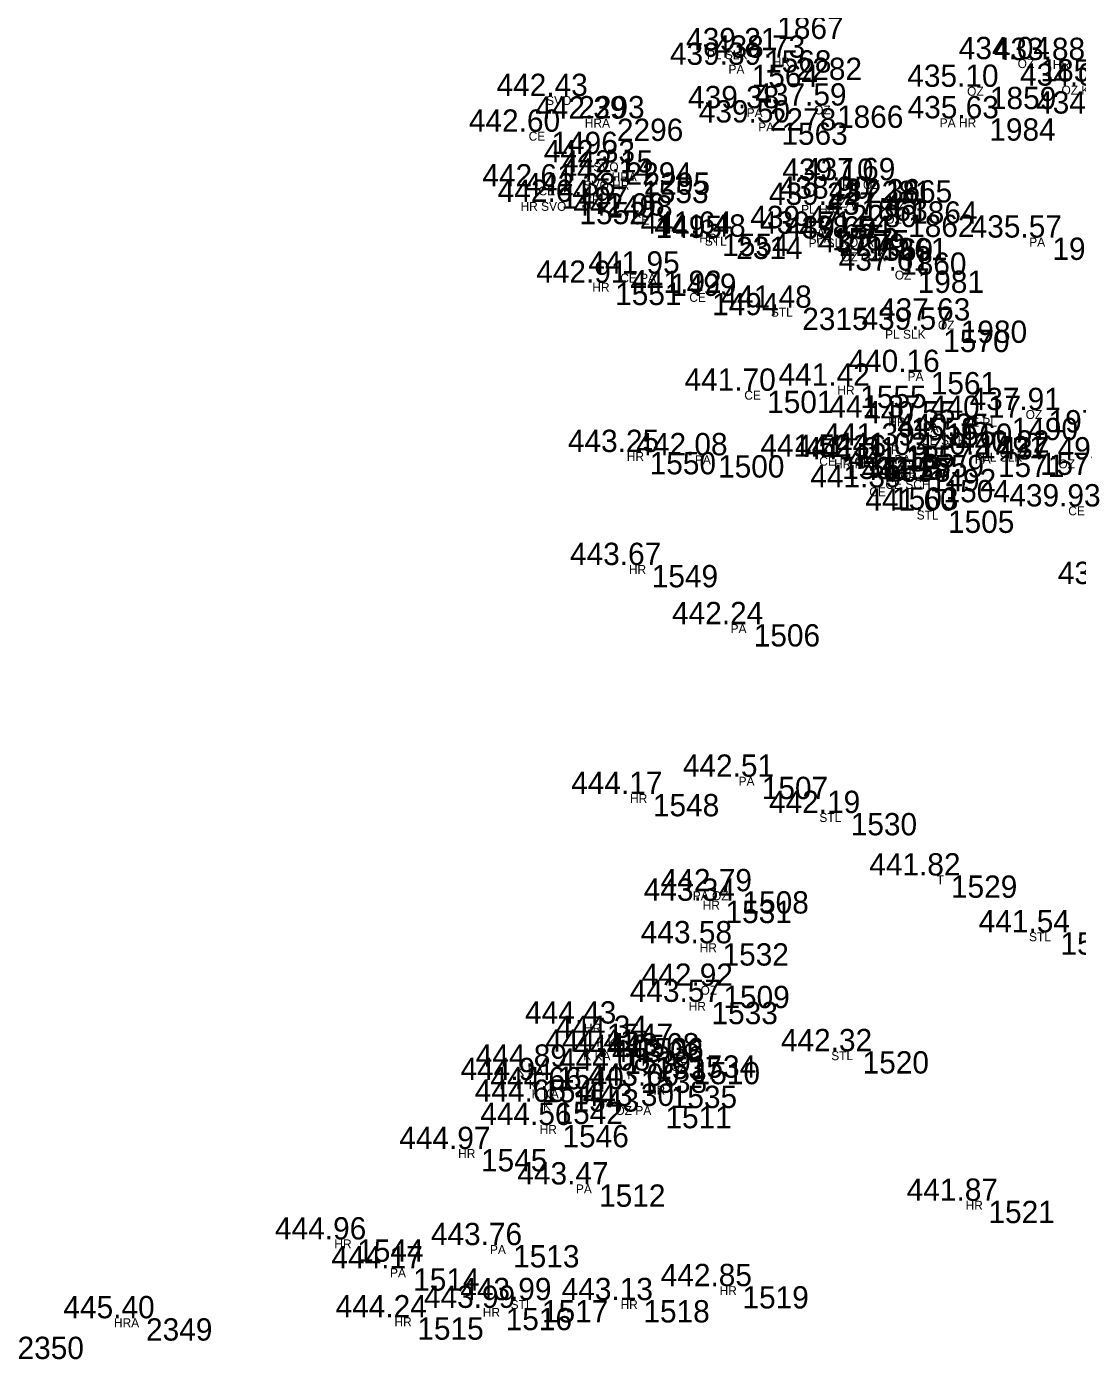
# Model space of a CAD drawing. Extents: x -639390 to -639075, y -1138747 to -1138358.
# Drawn here: x -639325.37 to -639290.05, y -1138561.86 to -1138517.05 of the extents above; entities that cross this region are included whole.
import ezdxf

# ---------------------------------------------------------------- set-up
doc = ezdxf.new("R2010")
doc.units = 0
for name, color, linetype in [('Vrstva 11', 7, 'Continuous'), ('Vrstva 12', 7, 'Continuous'), ('Vrstva 13', 7, 'Continuous'), ('Vrstva 57', 7, 'Continuous')]:
    doc.layers.add(name, color=color, linetype=linetype)

msp = doc.modelspace()

# ---------------------------------------------------------------- linework, layer by layer
at = {"layer": 'Vrstva 11'}
for p, q in [((-639300.83, -1138517.84), (-639300.83, -1138517.84)), ((-639301.28, -1138518.33), (-639301.28, -1138518.33)), ((-639299.8, -1138518.09), (-639299.8, -1138518.09)), ((-639291.57, -1138518.14), (-639291.57, -1138518.14)), ((-639290.39, -1138518.17), (-639290.39, -1138518.17)), ((-639307.11, -1138519.38), (-639307.11, -1138519.38)), ((-639293.27, -1138519.07), (-639293.27, -1138519.07)), ((-639300.67, -1138519.79), (-639300.67, -1138519.79)), ((-639298.41, -1138519.7), (-639298.41, -1138519.7)), ((-639305.81, -1138520.14), (-639305.81, -1138520.14)), ((-639300.28, -1138520.27), (-639300.28, -1138520.27)), ((-639293.29, -1138520.13), (-639293.29, -1138520.13)), ((-639308.01, -1138520.58), (-639308.01, -1138520.58)), ((-639305.52, -1138521.61), (-639305.52, -1138521.61)), ((-639304.91, -1138521.95), (-639304.91, -1138521.95)), ((-639307.68, -1138522.42), (-639307.68, -1138522.42)), ((-639304.96, -1138522.23), (-639304.96, -1138522.23)), ((-639297.47, -1138522.23), (-639297.47, -1138522.23)), ((-639296.77, -1138522.21), (-639296.77, -1138522.21)), ((-639307.07, -1138522.94), (-639307.07, -1138522.94)), ((-639306.17, -1138522.72), (-639306.17, -1138522.72)), ((-639297.59, -1138522.83), (-639297.59, -1138522.83)), ((-639295.92, -1138522.92), (-639295.92, -1138522.92)), ((-639304.51, -1138523.4), (-639304.51, -1138523.4)), ((-639297.95, -1138523.04), (-639297.95, -1138523.04)), ((-639296.02, -1138523.37), (-639296.02, -1138523.37)), ((-639298.58, -1138523.82), (-639298.58, -1138523.82)), ((-639302.27, -1138524.01), (-639302.27, -1138524.01)), ((-639301.8, -1138524.11), (-639301.8, -1138524.11)), ((-639298.34, -1138524.01), (-639298.34, -1138524.01)), ((-639297.41, -1138524.17), (-639297.41, -1138524.17)), ((-639296.93, -1138524.15), (-639296.93, -1138524.15)), ((-639291.17, -1138524.14), (-639291.17, -1138524.14)), ((-639296.29, -1138524.64), (-639296.29, -1138524.64)), ((-639304.02, -1138525.35), (-639304.02, -1138525.35)), ((-639295.7, -1138525.25), (-639295.7, -1138525.25)), ((-639305.87, -1138525.66), (-639305.87, -1138525.66)), ((-639302.61, -1138526), (-639302.61, -1138526)), ((-639299.58, -1138526.5), (-639299.58, -1138526.5)), ((-639294.25, -1138526.93), (-639294.25, -1138526.93)), ((-639294.84, -1138527.24), (-639294.84, -1138527.24)), ((-639295.26, -1138528.66), (-639295.26, -1138528.66)), ((-639297.63, -1138529.12), (-639297.63, -1138529.12)), ((-639300.76, -1138529.29), (-639300.76, -1138529.29)), ((-639291.3, -1138529.94), (-639291.3, -1138529.94)), ((-639295.92, -1138530.19), (-639295.92, -1138530.19)), ((-639294.75, -1138530.39), (-639294.75, -1138530.39)), ((-639292.54, -1138530.2), (-639292.54, -1138530.2)), ((-639293.63, -1138530.81), (-639293.63, -1138530.81)), ((-639304.71, -1138531.35), (-639304.71, -1138531.35)), ((-639302.41, -1138531.46), (-639302.41, -1138531.46)), ((-639296.12, -1138531.13), (-639296.12, -1138531.13)), ((-639295.7, -1138531.45), (-639295.7, -1138531.45)), ((-639293, -1138531.44), (-639293, -1138531.44)), ((-639291.59, -1138531.37), (-639291.59, -1138531.37)), ((-639298.24, -1138531.51), (-639298.24, -1138531.51)), ((-639297.06, -1138531.52), (-639297.06, -1138531.52)), ((-639296.83, -1138531.6), (-639296.83, -1138531.6)), ((-639295.29, -1138531.92), (-639295.29, -1138531.92)), ((-639290.2, -1138531.6), (-639290.2, -1138531.6)), ((-639294.83, -1138532.29), (-639294.83, -1138532.29)), ((-639296.56, -1138532.54), (-639296.56, -1138532.54)), ((-639294.68, -1138533.32), (-639294.68, -1138533.32)), ((-639304.64, -1138535.15), (-639304.64, -1138535.15)), ((-639301.21, -1138537.14), (-639301.21, -1138537.14)), ((-639300.94, -1138542.27), (-639300.94, -1138542.27)), ((-639304.6, -1138542.85), (-639304.6, -1138542.85)), ((-639297.95, -1138543.49), (-639297.95, -1138543.49)), ((-639294.58, -1138545.59), (-639294.58, -1138545.59)), ((-639301.59, -1138546.12), (-639301.59, -1138546.12)), ((-639302.16, -1138546.44), (-639302.16, -1138546.44)), ((-639290.9, -1138547.5), (-639290.9, -1138547.5)), ((-639302.26, -1138547.87), (-639302.26, -1138547.87)), ((-639302.23, -1138549.3), (-639302.23, -1138549.3)), ((-639302.63, -1138549.84), (-639302.63, -1138549.84)), ((-639306.15, -1138550.57), (-639306.15, -1138550.57)), ((-639305.12, -1138551.05), (-639305.12, -1138551.05)), ((-639305.56, -1138551.51), (-639305.56, -1138551.51)), ((-639303.36, -1138551.64), (-639303.36, -1138551.64)), ((-639297.55, -1138551.5), (-639297.55, -1138551.5)), ((-639307.81, -1138552.02), (-639307.81, -1138552.02)), ((-639304.52, -1138551.69), (-639304.52, -1138551.69)), ((-639303.23, -1138551.86), (-639303.23, -1138551.86)), ((-639308.32, -1138552.47), (-639308.32, -1138552.47)), ((-639305.01, -1138552.15), (-639305.01, -1138552.15)), ((-639307.3, -1138552.78), (-639307.3, -1138552.78)), ((-639304, -1138552.66), (-639304, -1138552.66)), ((-639307.84, -1138553.2), (-639307.84, -1138553.2)), ((-639304.18, -1138553.34), (-639304.18, -1138553.34)), ((-639307.64, -1138553.98), (-639307.64, -1138553.98)), ((-639310.38, -1138554.79), (-639310.38, -1138554.79)), ((-639306.41, -1138555.98), (-639306.41, -1138555.98)), ((-639293.32, -1138556.53), (-639293.32, -1138556.53)), ((-639314.54, -1138557.83), (-639314.54, -1138557.83)), ((-639309.3, -1138558.02), (-639309.3, -1138558.02)), ((-639312.66, -1138558.8), (-639312.66, -1138558.8)), ((-639301.59, -1138559.4), (-639301.59, -1138559.4)), ((-639309.55, -1138560.13), (-639309.55, -1138560.13)), ((-639308.33, -1138559.87), (-639308.33, -1138559.87)), ((-639304.92, -1138559.87), (-639304.92, -1138559.87)), ((-639321.64, -1138560.48), (-639321.64, -1138560.48)), ((-639312.52, -1138560.45), (-639312.52, -1138560.45))]:
    msp.add_line(p, q, dxfattribs=at)

# ---------------------------------------------------------------- texts
at = {"layer": 'Vrstva 12'}
for s, p in [('439.21 ', (-639303.205, -1138517.84)), ('439.39 ', (-639303.749, -1138518.33)), ('438.73 ', (-639302.269, -1138518.09)), ('434.04 ', (-639294.039, -1138518.14)), ('433.88 ', (-639292.859, -1138518.17)), ('435.10 ', (-639295.769, -1138519.07)), ('434.09 ', (-639291.979, -1138519.03)), ('442.43 ', (-639309.579, -1138519.38)), ('442.39 ', (-639308.279, -1138520.14)), ('439.38 ', (-639303.139, -1138519.79)), ('437.59 ', (-639300.879, -1138519.7)), ('435.63 ', (-639295.759, -1138520.13)), ('434.43 ', (-639291.439, -1138519.97)), ('442.60 ', (-639310.509, -1138520.58)), ('439.50 ', (-639302.779, -1138520.27)), ('442.33 ', (-639307.989, -1138521.61)), ('442.14 ', (-639307.429, -1138522.23)), ('442.15 ', (-639307.38, -1138521.95)), ('439.10 ', (-639299.969, -1138522.23)), ('437.69 ', (-639299.239, -1138522.21)), ('442.61 ', (-639310.055, -1138522.42)), ('442.38 ', (-639308.639, -1138522.72)), ('438.90 ', (-639300.089, -1138522.83)), ('442.64 ', (-639309.539, -1138522.94)), ('439.22 ', (-639300.419, -1138523.04)), ('437.36 ', (-639298.406, -1138522.92)), ('442.06 ', (-639306.996, -1138523.4)), ('437.45 ', (-639298.49, -1138523.37)), ('441.64 ', (-639304.739, -1138524.01)), ('441.48 ', (-639304.269, -1138524.11)), ('439.47 ', (-639301.049, -1138523.82)), ('439.71 ', (-639300.715, -1138524.01)), ('439.69 ', (-639299.879, -1138524.17)), ('438.54 ', (-639299.399, -1138524.15)), ('435.57 ', (-639293.639, -1138524.14)), ('437.75 ', (-639298.76, -1138524.64)), ('441.95 ', (-639306.49, -1138525.35)), ('437.61 ', (-639298.075, -1138525.25)), ('442.91 ', (-639308.245, -1138525.66)), ('441.92 ', (-639305.079, -1138526)), ('441.48 ', (-639302.049, -1138526.5)), ('439.57 ', (-639297.309, -1138527.24)), ('437.63 ', (-639296.719, -1138526.93)), ('440.16 ', (-639297.746, -1138528.66)), ('441.70 ', (-639303.259, -1138529.29)), ('441.42 ', (-639300.099, -1138529.12)), ('437.91 ', (-639293.675, -1138529.94)), ('441.37 ', (-639298.389, -1138530.19)), ('440.55 ', (-639297.22, -1138530.39)), ('440.17 ', (-639295.009, -1138530.2)), ('440.35 ', (-639296.1, -1138530.81)), ('443.25 ', (-639307.18, -1138531.35)), ('441.39 ', (-639298.589, -1138531.13)), ('442.08 ', (-639304.879, -1138531.46)), ('441.52 ', (-639300.709, -1138531.51)), ('441.36 ', (-639299.546, -1138531.52)), ('441.31 ', (-639299.205, -1138531.6)), ('441.03 ', (-639298.169, -1138531.45)), ('440.27 ', (-639295.469, -1138531.44)), ('440.22 ', (-639294.059, -1138531.37)), ('437.49 ', (-639292.669, -1138531.6)), ('441.18 ', (-639297.759, -1138531.92)), ('441.39 ', (-639299.029, -1138532.54)), ('441.27 ', (-639297.299, -1138532.29)), ('441.60 ', (-639297.179, -1138533.32)), ('439.93 ', (-639292.339, -1138533.18)), ('443.67 ', (-639307.109, -1138535.15)), ('439.69 ', (-639290.709, -1138535.79)), ('442.24 ', (-639303.679, -1138537.14)), ('442.51 ', (-639303.315, -1138542.27)), ('444.17 ', (-639307.069, -1138542.85)), ('442.19 ', (-639300.419, -1138543.49)), ('441.82 ', (-639297.049, -1138545.59)), ('442.79 ', (-639304.059, -1138546.12)), ('443.34 ', (-639304.629, -1138546.44)), ('443.58 ', (-639304.729, -1138547.87)), ('441.54 ', (-639293.369, -1138547.5)), ('442.92 ', (-639304.699, -1138549.3)), ('443.57 ', (-639305.099, -1138549.84)), ('444.43 ', (-639308.619, -1138550.57)), ('444.34 ', (-639307.589, -1138551.05)), ('442.32 ', (-639300.019, -1138551.5)), ('444.41 ', (-639307.935, -1138551.51)), ('444.05 ', (-639306.99, -1138551.69)), ('443.68 ', (-639305.829, -1138551.64)), ('443.08 ', (-639305.699, -1138551.86)), ('444.89 ', (-639310.279, -1138552.02)), ('444.08 ', (-639307.479, -1138552.15)), ('444.94 ', (-639310.789, -1138552.47)), ('444.66 ', (-639309.786, -1138552.78)), ('443.60 ', (-639306.499, -1138552.66)), ('444.65 ', (-639310.31, -1138553.2)), ('443.30 ', (-639306.679, -1138553.34)), ('444.56 ', (-639310.126, -1138553.98)), ('444.97 ', (-639312.849, -1138554.79)), ('443.47 ', (-639308.879, -1138555.98)), ('441.87 ', (-639295.789, -1138556.53)), ('444.96 ', (-639317.026, -1138557.83)), ('443.76 ', (-639311.786, -1138558.02)), ('444.17 ', (-639315.129, -1138558.8)), ('442.85 ', (-639304.06, -1138559.4)), ('443.99 ', (-639310.799, -1138559.87)), ('443.13 ', (-639307.389, -1138559.87)), ('444.24 ', (-639314.989, -1138560.45)), ('443.99 ', (-639312.019, -1138560.13)), ('445.40 ', (-639324.139, -1138560.48))]:
    msp.add_text(s, height=0.75, dxfattribs=at).set_placement(p)
at = {"layer": 'Vrstva 13'}
for s, p in [(' 1867', (-639300.42, -1138517.46)), (' 1568', (-639300.83, -1138518.59)), (' 1564', (-639301.28, -1138519.08)), (' 2282', (-639299.8, -1138518.84)), (' 1858', (-639291.57, -1138518.89)), (' 2293', (-639307.11, -1138520.13)), (' 1859', (-639293.27, -1138519.82)), (' 2278', (-639300.67, -1138520.54)), (' 1866', (-639298.41, -1138520.45)), (' 2296', (-639305.81, -1138520.89)), (' 1563', (-639300.28, -1138521.02)), (' 1984', (-639293.29, -1138520.88)), (' 1496', (-639308.01, -1138521.33)), (' 2294', (-639305.52, -1138522.36)), (' 2295', (-639304.91, -1138522.7)), (' 1497', (-639307.68, -1138523.17)), (' 1553', (-639304.96, -1138522.98)), (' 2281', (-639297.47, -1138522.98)), (' 1865', (-639296.77, -1138522.96)), (' 1552', (-639307.07, -1138523.69)), (' 1498', (-639306.17, -1138523.47)), (' 1863', (-639297.59, -1138523.58)), (' 1864', (-639295.92, -1138523.67)), (' 1495', (-639304.51, -1138524.15)), (' 2280', (-639297.95, -1138523.79)), (' 1862', (-639296.02, -1138524.12)), (' 1562', (-639298.58, -1138524.57)), (' 1554', (-639302.27, -1138524.76)), (' 2314', (-639301.8, -1138524.86)), (' 2279', (-639298.34, -1138524.76)), (' 1569', (-639297.41, -1138524.92)), (' 1861', (-639296.93, -1138524.9)), (' 1983', (-639291.17, -1138524.89)), (' 1860', (-639296.29, -1138525.39)), (' 1499', (-639304.02, -1138526.1)), (' 1981', (-639295.7, -1138526)), (' 1551', (-639305.87, -1138526.41)), (' 1494', (-639302.61, -1138526.75)), (' 2315', (-639299.58, -1138527.25)), (' 1980', (-639294.25, -1138527.68)), (' 1570', (-639294.84, -1138527.99)), (' 1561', (-639295.26, -1138529.41)), (' 1555', (-639297.63, -1138529.87)), (' 1501', (-639300.76, -1138530.04)), (' 1979', (-639291.3, -1138530.69)), (' 1556', (-639295.92, -1138530.94)), (' 1560', (-639294.75, -1138531.14)), (' 1490', (-639292.54, -1138530.95)), (' 1491', (-639293.63, -1138531.56)), (' 1550', (-639304.71, -1138532.1)), (' 1500', (-639302.41, -1138532.21)), (' 1557', (-639296.12, -1138531.88)), (' 1559', (-639295.7, -1138532.2)), (' 1571', (-639293, -1138532.19)), (' 1572', (-639291.59, -1138532.12)), (' 1502', (-639298.24, -1138532.26)), (' 1493', (-639297.06, -1138532.27)), (' 1558', (-639296.83, -1138532.35)), (' 1492', (-639295.29, -1138532.67)), (' 1504', (-639294.83, -1138533.04)), (' 1503', (-639296.56, -1138533.29)), (' 1505', (-639294.68, -1138534.07)), (' 1549', (-639304.64, -1138535.9)), (' 1506', (-639301.21, -1138537.89)), (' 1507', (-639300.94, -1138543.02)), (' 1548', (-639304.6, -1138543.6)), (' 1530', (-639297.95, -1138544.24)), (' 1529', (-639294.58, -1138546.34)), (' 1508', (-639301.59, -1138546.87)), (' 1531', (-639302.16, -1138547.19)), (' 1528', (-639290.9, -1138548.25)), (' 1532', (-639302.26, -1138548.62)), (' 1509', (-639302.23, -1138550.05)), (' 1533', (-639302.63, -1138550.59)), (' 1547', (-639306.15, -1138551.32)), (' 1536', (-639305.12, -1138551.8)), (' 1539', (-639305.56, -1138552.26)), (' 1534', (-639303.36, -1138552.39)), (' 1520', (-639297.55, -1138552.25)), (' 1540', (-639307.81, -1138552.77)), (' 1537', (-639304.52, -1138552.44)), (' 1510', (-639303.23, -1138552.61)), (' 1541', (-639308.32, -1138553.22)), (' 1538', (-639305.01, -1138552.9)), (' 1543', (-639307.3, -1138553.53)), (' 1535', (-639304, -1138553.41)), (' 1542', (-639307.84, -1138553.95)), (' 1511', (-639304.18, -1138554.09)), (' 1546', (-639307.64, -1138554.73)), (' 1545', (-639310.38, -1138555.54)), (' 1512', (-639306.41, -1138556.73)), (' 1521', (-639293.32, -1138557.28)), (' 1544', (-639314.54, -1138558.58)), (' 1513', (-639309.3, -1138558.77)), (' 1514', (-639312.66, -1138559.55)), (' 1519', (-639301.59, -1138560.15)), (' 1516', (-639309.55, -1138560.88)), (' 1517', (-639308.33, -1138560.62)), (' 1518', (-639304.92, -1138560.62)), (' 2349', (-639321.64, -1138561.23)), (' 1515', (-639312.52, -1138561.2)), (' 2350', (-639325.96, -1138561.85))]:
    msp.add_text(s, height=0.75, dxfattribs=at).set_placement(p)
at = {"layer": 'Vrstva 57'}
for s, p in [('PL SLK', (-639302.505, -1138518.14)), ('PA', (-639301.78, -1138518.63)), ('HR', (-639300.289, -1138518.39)), ('OZ', (-639292.059, -1138518.44)), ('HR', (-639290.879, -1138518.47)), ('SVO', (-639307.911, -1138519.68)), ('OZ', (-639293.759, -1138519.37)), ('OZ K', (-639290.585, -1138519.33)), ('PA', (-639301.17, -1138520.09)), ('OZ', (-639298.899, -1138520)), ('HRA', (-639306.61, -1138520.44)), ('PA', (-639300.78, -1138520.57)), ('PA HR', (-639294.679, -1138520.43)), ('CE', (-639308.498, -1138520.88)), ('SVO', (-639306.321, -1138521.91)), ('HRA', (-639305.71, -1138522.25)), ('CE', (-639308.167, -1138522.72)), ('SVO HR', (-639306.649, -1138522.53)), ('HR', (-639297.959, -1138522.53)), ('OZ', (-639297.259, -1138522.51)), ('HR SVO', (-639308.771, -1138523.24)), ('CE', (-639306.657, -1138523.02)), ('OZA', (-639298.39, -1138523.13)), ('OZ', (-639296.409, -1138523.22)), ('CE', (-639304.998, -1138523.7)), ('PL HR', (-639299.339, -1138523.34)), ('OZ', (-639296.509, -1138523.67)), ('PA', (-639299.08, -1138524.12)), ('HR', (-639302.759, -1138524.31)), ('STL', (-639302.575, -1138524.41)), ('PL SLK', (-639299.085, -1138524.47)), ('PA', (-639298.84, -1138524.31)), ('OZA', (-639297.73, -1138524.45)), ('PA', (-639291.67, -1138524.44)), ('OZ OZA', (-639297.99, -1138524.94)), ('CE PA', (-639305.42, -1138525.65)), ('OZ', (-639296.189, -1138525.55)), ('HR', (-639306.359, -1138525.96)), ('CE', (-639303.098, -1138526.3)), ('STL', (-639300.355, -1138526.8)), ('OZ', (-639294.739, -1138527.23)), ('PL SLK', (-639296.515, -1138527.54)), ('PA', (-639295.76, -1138528.96)), ('HR', (-639298.119, -1138529.42)), ('CE', (-639301.248, -1138529.59)), ('OZ', (-639291.789, -1138530.24)), ('HR', (-639296.409, -1138530.49)), ('PA', (-639295.25, -1138530.69)), ('CE PL', (-639293.915, -1138530.5)), ('CE SCH', (-639295.305, -1138531.11)), ('HR', (-639305.199, -1138531.65)), ('PA', (-639302.91, -1138531.76)), ('HR', (-639296.609, -1138531.43)), ('PA', (-639296.2, -1138531.75)), ('PA', (-639293.5, -1138531.74)), ('PL SLK', (-639293.265, -1138531.67)), ('CE', (-639298.728, -1138531.81)), ('HR PA', (-639298.23, -1138531.9)), ('CE', (-639297.547, -1138531.82)), ('SCH CE', (-639296.978, -1138532.22)), ('OZ', (-639290.689, -1138531.9)), ('CE SCH', (-639296.505, -1138532.59)), ('CE', (-639297.047, -1138532.84)), ('CE', (-639290.358, -1138533.48)), ('STL', (-639295.455, -1138533.62)), ('HR', (-639305.129, -1138535.45)), ('PA', (-639301.71, -1138537.44)), ('PA', (-639301.44, -1138542.57)), ('HR', (-639305.089, -1138543.15)), ('STL', (-639298.725, -1138543.79)), ('T', (-639294.78, -1138545.89)), ('PA OZ', (-639302.979, -1138546.42)), ('HR', (-639302.649, -1138546.74)), ('STL', (-639291.675, -1138547.8)), ('HR', (-639302.749, -1138548.17)), ('OZ', (-639302.719, -1138549.6)), ('HR', (-639303.119, -1138550.14)), ('HR', (-639306.639, -1138550.87)), ('K KA', (-639306.22, -1138551.35)), ('K KA', (-639306.66, -1138551.81)), ('HR', (-639303.849, -1138551.94)), ('STL', (-639298.325, -1138551.8)), ('K KA', (-639308.91, -1138552.32)), ('K', (-639304.695, -1138551.99)), ('OZ', (-639303.719, -1138552.16)), ('K', (-639308.495, -1138552.77)), ('K', (-639305.185, -1138552.45)), ('K KA', (-639308.4, -1138553.08)), ('HR', (-639304.489, -1138552.96)), ('K', (-639308.015, -1138553.5)), ('OZ PA', (-639305.58, -1138553.64)), ('HR', (-639308.129, -1138554.28)), ('HR', (-639310.869, -1138555.09)), ('PA', (-639306.91, -1138556.28)), ('HR', (-639293.809, -1138556.83)), ('HR', (-639315.029, -1138558.13)), ('PA', (-639309.8, -1138558.32)), ('PA', (-639313.16, -1138559.1)), ('HR', (-639302.079, -1138559.7)), ('HR', (-639310.039, -1138560.43)), ('STL', (-639309.105, -1138560.17)), ('HR', (-639305.409, -1138560.17)), ('HRA', (-639322.44, -1138560.78)), ('HR', (-639313.009, -1138560.75))]:
    msp.add_text(s, height=0.3, dxfattribs=at).set_placement(p)

doc.saveas('drawing.dxf')
